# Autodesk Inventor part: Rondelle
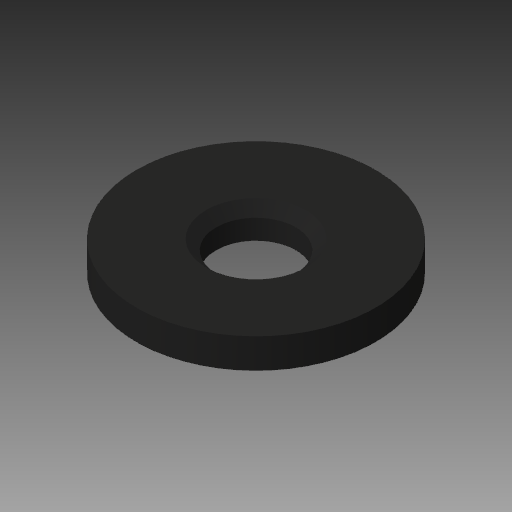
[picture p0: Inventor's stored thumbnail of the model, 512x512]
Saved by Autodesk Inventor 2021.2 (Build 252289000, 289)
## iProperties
Created: 2018-06
Part Number: Rondelle
Material: Caoutchouc
Document SubType Name: Modeling
Designer: Fabian Perrée
Density: 0.93 g/cm^3
Appearance: Caoutchouc - Noir
Author: Fabian Perrée
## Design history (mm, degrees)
sketch "Esquisse1"
  geometry: C1 r 6 at (0, 0); C2 r 2 at (0, 0); 1 further point
  constraints: 2 centre point, 2 coincident
  dimensions: "d0" = 12 diameter of C1; "d1" = 4 diameter of C2
extrude "Extrusion1" new body sketch "Esquisse1" distance "d2" = 1.5; taper "d3" = 0 deg
chamfer "Chanfrein1" distance "d4" = 0.5; stored, may be unused: second distance "d5" = 2, angle "d6" = 45 deg
node "Solide1"
